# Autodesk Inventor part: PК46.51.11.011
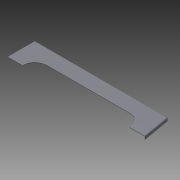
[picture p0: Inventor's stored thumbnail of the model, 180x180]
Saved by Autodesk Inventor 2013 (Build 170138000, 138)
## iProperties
Shininess: 64.0
Length Units: 11269
Angle Units: 11279
Time Units: 11290
Mass Units: 11283
Length Display Precision: 3
Angle Display Precision: 2
Compacted: True
Part Number: PК46.51.11.011
Document SubType Name: Листовой материал
Created: 2005-02
Material: Steel, Mild
Designer: =<Author>
Manufacturer: Standard
Standards Organization: Custom
Description: Top Plate
Density: 7.86 g/cm^3
Flat Pattern Width: 12.0524 cm
Flat Pattern Length: 57.6528 cm
Flat Pattern Area: 694.854 cm^2
Sheet Metal Rule: По умолчанию
Mass: 747.318 g
Surface Area: 979.657 cm^2
Volume: 95.0786 cm^3
Density: 0.0
Volumn: 0.0
Area: 0.0
PropertySet Name: Model Information
Control State: 0
Master: False
Checked Out: False
Checked Out Date: 2008-10-15
Last Check In Date: 2008-10-15
Толщина: 2.000 mm
Радиус_гибки: 2.000 mm
Ширина_просечки: 2.000 mm
Глубина_просечки: 1.000 mm
Размер_высечки: 8.000 mm
Минимальный_остаток: 4.000 mm
Радиус_перехода: 2.000 mm
JacobiRadiusSize: 2.000 mm
GapSize: 2.000 mm
d0: 540.000 mm
d2: 62.000 mm
d9: 2.000 mm
d10: 2.000 mm
d11: 1.000 mm
d12: 4.000 mm
d13: 2.000 mm
d14: 10.000 mm
d15: 90.00 deg
d16: 2.000 mm
d17: 99.93 deg
d19: 62.000 mm
d20: 50.000 mm
d21: 62.000 mm
d22: 2.000 mm
d23: 1.000 mm
d24: 4.000 mm
d25: 2.000 mm
d26: 10.000 mm
d27: 90.00 deg
d28: 2.000 mm
d29: 8.000 mm
d30: 2.000 mm
d31: 0.100 mm
d32: 0.000 mm
d33: 2.000 mm
d34: 1.000 mm
d35: 4.000 mm
d36: 2.000 mm
d37: 10.000 mm
d38: 90.00 deg
d39: 2.000 mm
d40: 8.000 mm
d41: 2.000 mm
d42: 0.100 mm
d43: 0.000 mm
Author: PVitaliy
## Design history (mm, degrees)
node "Грань1"
node "Фланец1"
node "Фланец2"
feature "УглСтык1" dims "d29" = 8 (= Размер_высечки), "d30" = 2 (= Радиус_гибки), "d31" = 0.1, "d32" = 0, "Толщина" = 2
node "Фланец3"
feature "УглСтык2" dims "d40" = 8 (= Размер_высечки), "d41" = 2 (= Радиус_гибки), "d42" = 0.1, "d43" = 0, "Толщина" = 2
body "Solid1"
sketch "Эскиз1"
  geometry: L1 (0, 0)-(540, 0); L2 (445.904, -62)-(112, -62); L3 (0, 0)-(0, -112); L4 (540, 0)-(559.608, -112); L5 (495.155, -103.378)-(496.665, -112); L6 (62, -112)-(0, -112); L7 (496.665, -112)-(559.608, -112); A1 r 50 centre (112, -112) between (112, -62) and (62, -112); A2 r 50 centre (445.904, -112) between (495.155, -103.378) and (445.904, -62)
  constraints: 14 end point, 4 point on circle, 3 tangent, 2 centre point, 2 collinear, 2 parallel, 2 perpendicular, 1 equal radius, 1 horizontal, 1 point on line, 1 other
  dimensions: "d0" = 540 distance of L1.start L1.end; "d2" = 62 distance between parallel lines of L2 L1; "d17" = 99.93 deg angle of L4 L1; "d19" = 62 distance between parallel lines of L4 L5; "d20" = 50 radius of A1; "d21" = 62 distance of L6.start L3.end
feature "Пластина1" dims "Толщина" = 2
sketch "Эскиз2"
  geometry: L1 through (-270, 0) direction (-1, 0); L2 (-540, 0)-(-540, -10); L3 (-540, -10)-(0, -10); L4 through (0, -5) direction (-0, 1)
  constraints: 6 end point, 1 horizontal, 1 perpendicular, 1 vertical
feature "Пластина2" dims "d10" = 2 (= Ширина_просечки), "d12" = 4 (= Минимальный_остаток), "d14" = 10, angle "d15" = 90 deg, "d16" = 2 (= Радиус_гибки), "Толщина" = 2
feature "Изгиб1" dims "d10" = 2 (= Ширина_просечки), "d11" = 1 (= Глубина_просечки), "d12" = 4 (= Минимальный_остаток), "d13" = 2 (= Радиус_гибки), "d14" = 10, angle "d15" = 90 deg, "d16" = 2 (= Радиус_гибки), "Толщина" = 2, "Зазор_стыка" = 0.01
sketch "Эскиз3"
  geometry: L1 through (-54, 0) direction (-1, 3.65e-34); L2 (-108, 0)-(-108, -10); L3 (-108, -10)-(0, -10); L4 through (0, -5) direction (-9.87e-33, 1)
  constraints: 6 end point, 1 horizontal, 1 perpendicular, 1 vertical
feature "Пластина3" dims "d22" = 2 (= Ширина_просечки), "d24" = 4 (= Минимальный_остаток), "d26" = 10, angle "d27" = 90 deg, "d28" = 2 (= Радиус_гибки), "Толщина" = 2
feature "Изгиб2" dims "d22" = 2 (= Ширина_просечки), "d23" = 1 (= Глубина_просечки), "d24" = 4 (= Минимальный_остаток), "d25" = 2 (= Радиус_гибки), "d26" = 10, angle "d27" = 90 deg, "d28" = 2 (= Радиус_гибки), "Толщина" = 2, "Зазор_стыка" = 0.01
sketch "Эскиз4"
  geometry: L1 through (-54.821, 0) direction (-1, -2.25e-33); L2 (-109.643, 0)-(-109.643, -10); L3 (-109.643, -10)-(0, -10); L4 through (0, -5) direction (0, 1)
  constraints: 6 end point, 1 horizontal, 1 perpendicular, 1 vertical
feature "Пластина4" dims "d33" = 2 (= Ширина_просечки), "d35" = 4 (= Минимальный_остаток), "d37" = 10, angle "d38" = 90 deg, "d39" = 2 (= Радиус_гибки), "Толщина" = 2
feature "Изгиб3" dims "d33" = 2 (= Ширина_просечки), "d34" = 1 (= Глубина_просечки), "d35" = 4 (= Минимальный_остаток), "d36" = 2 (= Радиус_гибки), "d37" = 10, angle "d38" = 90 deg, "d39" = 2 (= Радиус_гибки), "Толщина" = 2, "Зазор_стыка" = 0.01
node "Развертка"
feature "FlatPatternExtrusion2" dims "d0" = 2 (derived)
other parameters: "Радиус_гибки" = 2 (= Толщина), "Ширина_просечки" = 2 (= Толщина), "Глубина_просечки" = 1 (= 0.5 x Толщина), "Размер_высечки" = 8 (= 4 x Толщина), "Минимальный_остаток" = 4 (= 2 x Толщина), "Радиус_перехода" = 2 (= Радиус_гибки), "d9" = 2 (= Радиус_гибки), "JacobiRadiusSize" = 2 (= Толщина), "GapSize" = 2 (= Толщина)
